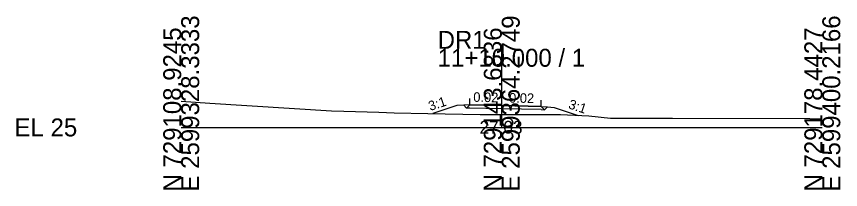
# Model space of a CAD drawing. Extents: x -26 to 1162, y -10 to 9515.
# Drawn here: x -25.7 to 102.8, y 5490.3 to 5517.3 of the extents above; entities that cross this region are included whole.
import ezdxf

# ---------------------------------------------------------------- set-up
doc = ezdxf.new("R2010")
doc.units = 0
for name, color, linetype in [('Exist Cross Section Cell', 7, 'Continuous'), ('Exist XS Center Line Elevation Label', 7, 'Continuous'), ('Exist XS Ground Line', 7, 'Continuous'), ('Prop XS Ditch Slope Text', 7, 'Continuous'), ('Prop XS Dump Level', 7, 'Continuous'), ('Prop XS EOT Tick Mark', 7, 'Continuous'), ('Prop XS Finish Grade', 7, 'Continuous'), ('Prop XS Finish Grade Earthwork', 7, 'Continuous'), ('Prop XS Finish Grade Pavement', 7, 'Continuous'), ('Prop XS Pvmt Edge Slope', 7, 'Continuous'), ('Prop XS SE Text', 7, 'Continuous'), ('Prop XS Subgrade Earthwork', 7, 'Continuous')]:
    doc.layers.add(name, color=color, linetype=linetype)

msp = doc.modelspace()

# ---------------------------------------------------------------- linework, layer by layer
at = {"layer": 'Exist Cross Section Cell'}
for p, q in [((50, 5500), (50, 5512.27)), ((0, 5500), (50, 5500)), ((50, 5500), (100, 5500))]:
    msp.add_line(p, q, dxfattribs=at)
at = {"layer": 'Exist XS Ground Line'}
msp.add_lwpolyline([(0, 5504.09), (4.48, 5503.78), (23.42, 5502.58), (25.35, 5502.52), (30.83, 5502.39), (33.24, 5502.29), (38.47, 5502.2), (46.64, 5502.03), (49.3, 5502.03), (50, 5502.03), (59.18, 5502), (63.58, 5501.79), (66.94, 5501.47), (73.92, 5501.46), (75.56, 5501.44), (76.61, 5501.44), (98.04, 5501.39), (100, 5501.35)], dxfattribs=at)
at = {"layer": 'Prop XS Dump Level'}
for p, q in [((50, 5503.41), (45, 5503.51)), ((45, 5503.51), (50, 5503.41)), ((56.16, 5503.28), (50, 5503.41)), ((50, 5503.41), (56.16, 5503.28))]:
    msp.add_line(p, q, dxfattribs=at)
at = {"layer": 'Prop XS EOT Tick Mark'}
for p, q in [((45, 5503.51), (45, 5504.51)), ((56.16, 5503.28), (56.16, 5504.28))]:
    msp.add_line(p, q, dxfattribs=at)
at = {"layer": 'Prop XS Finish Grade'}
for p, q in [((45, 5503.51), (44.06, 5503.47)), ((56.16, 5503.28), (57.14, 5503.21))]:
    msp.add_line(p, q, dxfattribs=at)
at = {"layer": 'Prop XS Finish Grade Earthwork'}
for p, q in [((43, 5503.43), (39.27, 5502.18)), ((44.06, 5503.47), (43, 5503.43)), ((57.14, 5503.21), (58.16, 5503.12)), ((58.16, 5503.12), (61.91, 5501.87))]:
    msp.add_line(p, q, dxfattribs=at)
at = {"layer": 'Prop XS Finish Grade Pavement'}
for p, q in [((45, 5503.51), (50, 5503.41)), ((50, 5503.41), (56.16, 5503.28))]:
    msp.add_line(p, q, dxfattribs=at)
at = {"layer": 'Prop XS Pvmt Edge Slope'}
for p, q in [((44.06, 5503.47), (44.51, 5503.02)), ((45, 5503.51), (44.51, 5503.02)), ((56.16, 5503.28), (56.67, 5502.77)), ((57.14, 5503.21), (56.67, 5502.77))]:
    msp.add_line(p, q, dxfattribs=at)
at = {"layer": 'Prop XS Subgrade Earthwork'}
for p, q in [((44.51, 5503.02), (44.06, 5503.47)), ((44.51, 5503.02), (44.06, 5503.47)), ((45, 5503.01), (44.51, 5503.02)), ((50, 5502.91), (45, 5503.01)), ((56.16, 5502.78), (50, 5502.91)), ((56.16, 5502.78), (56.67, 5502.77)), ((56.67, 5502.77), (57.14, 5503.21)), ((56.67, 5502.77), (57.14, 5503.21))]:
    msp.add_line(p, q, dxfattribs=at)

# ---------------------------------------------------------------- texts
at = {"layer": 'Exist Cross Section Cell'}
for s, p in [('E 2599328.3333', (2.8, 5490)), ('E 2599364.2749', (52.8, 5490)), ('E 2599400.2166', (102.8, 5490)), ('N 729108.9245', (0, 5490)), ('N 729143.6836', (50, 5490)), ('N 729178.4427', (100, 5490))]:
    msp.add_text(s, height=2.8, rotation=90, dxfattribs=at).set_placement(p)
for s, p in [('DR1', (40, 5512.27)), ('11+10.000 / 1', (40, 5509.47)), ('EL 25', (-26, 5498.6))]:
    msp.add_text(s, height=2.8, dxfattribs=at).set_placement(p)
at = {"layer": 'Exist XS Center Line Elevation Label'}
msp.add_text('27.03', height=2, dxfattribs=at).set_placement((46.54, 5499.03))
at = {"layer": 'Prop XS Ditch Slope Text'}
for rotation, p in [(18.4349, (38.85, 5502.56)), (341.5883, (60.29, 5503.01))]:
    msp.add_text('3:1', height=1.5, rotation=rotation, dxfattribs=at).set_placement(p)
at = {"layer": 'Prop XS Dump Level'}
for p in [(43, 5503.39), (58.16, 5503.08)]:
    msp.add_text('Case1', height=0.04, dxfattribs=at).set_placement(p)
at = {"layer": 'Prop XS SE Text'}
for p in [(45.55, 5504), (51.13, 5503.88)]:
    msp.add_text('0.02', height=1.5, rotation=358.8542, dxfattribs=at).set_placement(p)

doc.saveas('drawing.dxf')
